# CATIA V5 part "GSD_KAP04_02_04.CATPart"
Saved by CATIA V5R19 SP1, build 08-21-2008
Part number: GSD_KAP04_02_04
Definition: Beispielmodell für das Kapitel 4 - Sketcher.
Description: CATIA V5 Flächenmodellierung  Copyright (c) 2009 Maik Hertha IT Consultants
Bounding box of the stored display mesh (mm): x -135 to 40, y 0 to 0, z -55 to 55
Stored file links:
  \GSD_BUCH_UEBUNG\GSD_KAP04_02_04.CATPart
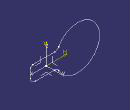
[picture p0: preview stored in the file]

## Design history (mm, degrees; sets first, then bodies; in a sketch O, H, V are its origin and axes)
AxisSystem1: origin (0, 0, 0), X (1, 0, 0), Y (0, 1, 0), Z (0, 0, 1)
Set1
  Sketch1 on zx-plane, origin (0, 0, 0), H (-1, 0, 0), V (0, 0, 1)
    point P1 (-35, 20)
    line L1 (-35, 20) -> (21.1357, 20)
    arc A1 centre (21.1357, 32) radius 12 from (21.1357, 20) to (31.6786, 26.2687) ccw
    arc A2 centre (80, 0) radius 55 from (31.6786, 26.2687) to (31.6786, -26.2687) cw
    point P5 (80, 0)
    arc A3 centre (21.1357, -32) radius 12 from (31.6786, -26.2687) to (21.1357, -20) ccw
    line L2 (21.1357, -20) -> (-28, -20)
    arc A4 centre (-28, -8) radius 12 from (-28, -20) to (-40, -8) cw
    line L3 (-40, -8) -> (-40, 15)
    line L4 (-40, 15) -> (-35, 20)
    radius A2 = 55
    radius A1 = 12
    radius A3 = 12
    radius A4 = 12
    distance P5 H = 0
    distance L1 L2 = 40
    distance P5 V = 80
    distance L3 V = 40
    distance L3 P1 = 5
    angle L4 L1 = 45
    tangency: A1 A2, A1 L1, A3 A2, A3 L2, A4 L2, A4 L3
    symmetry: L1 L2 H
    vertical: L3 V
Body1 (main body)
